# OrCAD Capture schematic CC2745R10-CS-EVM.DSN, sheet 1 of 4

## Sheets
1 1_RF: size A3; title: CC2745R10-CS-EVM
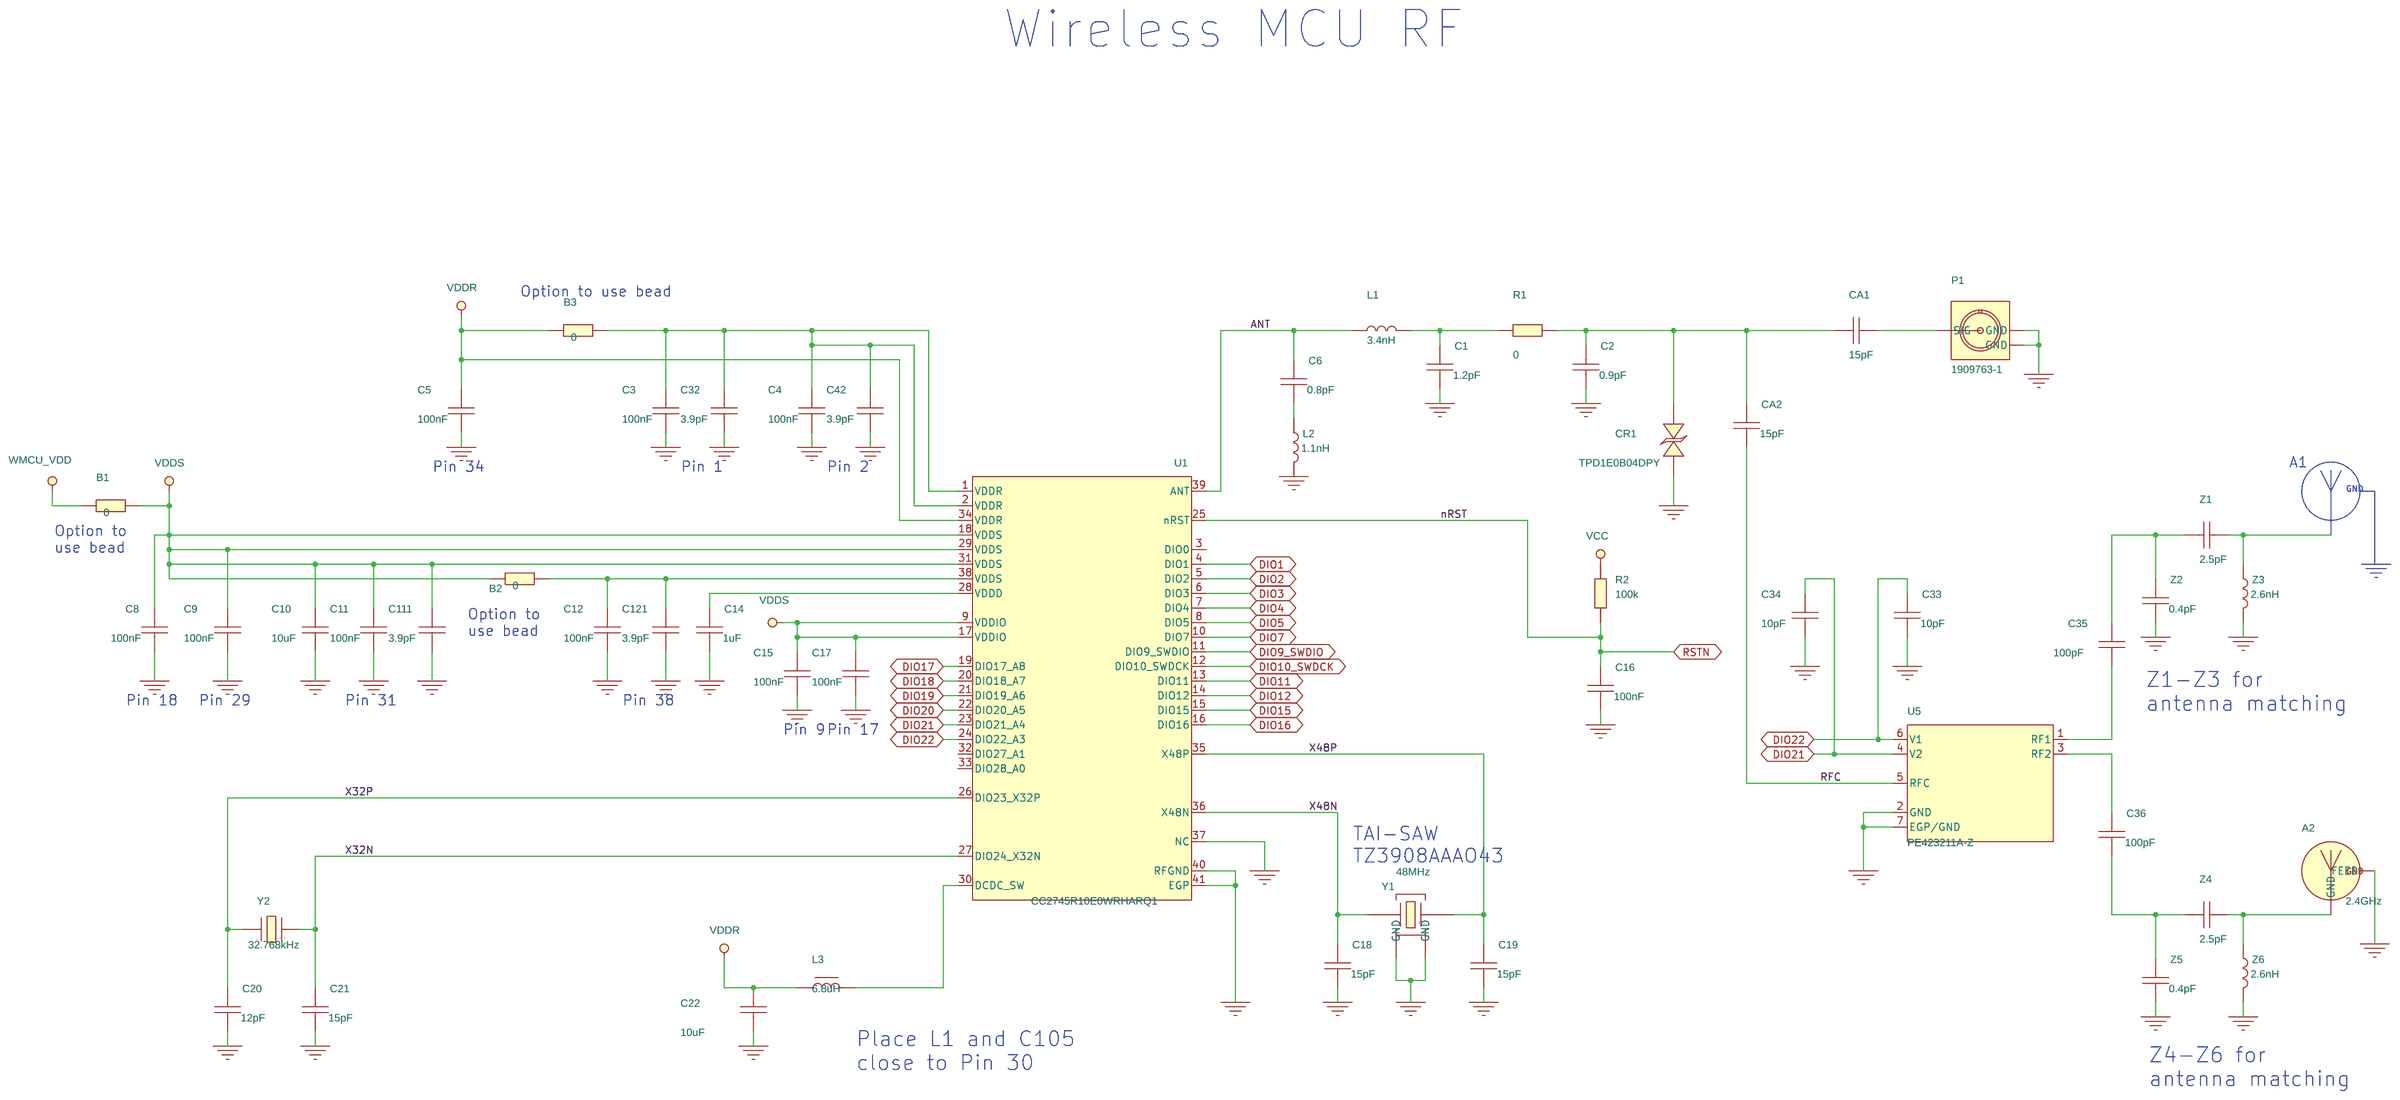
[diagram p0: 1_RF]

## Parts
A2  2.4GHz  [ANTENNA_AN043AN_B]
B1  0  [RESC0603X35B2N]
B2  0  [RESC0603X35B2N]
B3  0  [RESC0603X35B2N]
C1  1.2pF  [CAPC0603X35B2N]
C2  0.9pF  [CAPC0603X35B2N]
C3  100nF  [CAPC0603X35B2N]
C4  100nF  [CAPC0603X35B2N]
C5  100nF  [CAPC0603X35B2N]
C6  0.8pF  [CAPC0603X35B2N]
C8  100nF  [CAPC0603X35B2N]
C9  100nF  [CAPC0603X35B2N]
C10  10uF  [CAPC1608X100A2N]
C11  100nF  [CAPC0603X35B2N]
C12  100nF  [CAPC0603X35B2N]
C14  1uF  [CAPC1005X60B2N]
C15  100nF  [CAPC0603X35B2N]
C16  100nF  [CAPC0603X35B2N]
C17  100nF  [CAPC0603X35B2N]
C18  15pF  [CAPC0603X35B2N]
C19  15pF  [CAPC0603X35B2N]
C20  12pF  [CAPC0603X35B2N]
C21  15pF  [CAPC0603X35B2N]
C22  10uF  [CAPC1608X100A2N]
C32  3.9pF  [CAPC0603X35B2N]
C33  10pF  [CAPC0603X35B2N]
C34  10pF  [CAPC0603X35B2N]
C35  100pF  [CAPC0603X35B2N]
C36  100pF  [CAPC0603X35B2N]
C42  3.9pF  [CAPC0603X35B2N]
C111  3.9pF  [CAPC0603X35B2N]
C121  3.9pF  [CAPC0603X35B2N]
CA1  15pF  [CAPC0603X35B2N]
CA2  15pF  [CAPC0603X35B2N]
CR1  TPD1E0B04DPY  [SON65P100X60X45-2A2N]
L1  3.4nH  [INDC0603X33A2N]
L2  1.1nH  [INDC0603X33A2N]
L3  6.8uH  [INDC2012X150A2N]
P1  1909763-1  [TE_19097631_A2N]
R1  0  [RESC0603X35B2N]
R2  100k  [RESC0603X35B2N]
U1  CC2745R10E0WRHARQ1  [QFNFC50P600X600X100-41F2N]
U5  PE423211A-Z  [SON50P160X160X60-7C2N]
Y1  48MHz  [OSCCC205X165X50-4A2N]
Y2  32.768kHz  [XTAL_FC2012AA_A2N]
Z1  2.5pF  [CAPC0603X35B2N]
Z2  0.4pF  [CAPC0603X35B2N]
Z3  2.6nH  [INDC0603X33A2N]
Z4  2.5pF  [CAPC0603X35B2N]
Z5  0.4pF  [CAPC0603X35B2N]
Z6  2.6nH  [INDC0603X33A2N]

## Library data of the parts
A2 = ANTENNA_AN043: ANTENNA, NON COMPONENT, SMALL SIZE 2.4GHz PCB ANTENNA, NOT APPLY; ALT_SYMBOLS: ANTENNA_AN043AN_B_MIRROR,ANTENNA_AN043CN,ANTENNA_MIRROR_AN043CN; Additional Datasheet URL: N/A; CLASS: DISCRETE; Country of Origin: Missing Info; Datasheet URL: https://www.ti.com/lit/an/swra117d/swra117d.pdf; Mass: N/A; Maximum Operating Temperature: +85DEGC; Minimum Operating Temperature: -40DEGC; Mounting Type: NOT APPLY; NOTEfied URL: https://dev-webinterface.dpserver.no/item/7336948; Notes: Custom item designed upon client's request.; Packing Size: N/A; Packing Type: Missing Info; Part Number: 13-00290; Part Type: Mechanical|ANTENNA|NON COMPONENT; REACH/SVHC Compliance: Missing Info; REACH/SVHC Details: N/A; REACH/SVHC Source: N/A; REACH/SVHC Status: Missing Info; ROHS: Not Applicable; Status: Released; Texas Part Status: Under Review; Type: Mechanical; Vendor: TEXAS INSTRUMENTS; Vendor Part Number: AN043; Vendor Part Status: Active
B1-B3 R1 = RESISTOR: RESISTOR, THICK FILM, JUMPER, 0, 0R/+0.05R, 0.05W, 0.5A, -55DEGC/+155DEGC, 0201, SMD; ALT_SYMBOLS: RESC0603X35B2L,RESC0603X35B2M; Additional Datasheet URL: https://www.yageo.com/en/Home; Budgetary Price: .01936 USD; Country of Origin: Missing Info; Datasheet URL: https://www.yageo.com/upload/media/product/productsearch/datasheet/rchip/PYu-AF_51_RoHS_L_10.pdf; Lead Time: 18; Mass: N/A; Maximum Operating Temperature: +155DEGC; Maximum Temperature Coefficient: N/A; Maximum Tolerance: +0.05R; Minimum Operating Temperature: -55DEGC; Minimum Temperature Coefficient: N/A; Minimum Tolerance: 0R; Mounting Type: SMD; NOTEfied URL: https://dev-webinterface.dpserver.no/item/59954582; PCB Package: 0201; Packing Size: 50000; Packing Type: Tape & Reel; Part Number: 01-26238; Part Type: Resistor|0201|JUMPER; ROHS: Exempt; Rated Current: 0.5A; Rated Power: 0.05W; Resistor Type: THICK FILM; Status: Released; Texas Part Status: Under Review; Type: Resistor; Vendor: YAGEO; Vendor Part Number: AF0201JR-130RL; Vendor Part Status: Active
C1 = CAPACITOR: CAPACITOR, CERAMIC C0G/NP0, 1.2pF, 25V, -0.25pF/+0.25pF, -55DEGC/+125DEGC, 0201, SMD; ALT_SYMBOLS: CAPC0603X35B2L,CAPC0603X35B2M; Additional Datasheet URL: https://www.murata.com/en-us/products/productdetail?partno=GRT0335C1E1R2CA02%23; Budgetary Price: 0.005 EUR; Country of Origin: China,Japan,Philippines; Datasheet URL: https://search.murata.co.jp/Ceramy/image/img/A01X/G101/ENG/GRT0335C1E1R2CA02-01A.pdf; Dielectric Type: C0G/NP0; Lead Time: 12; Mass: 0.00033g; Maximum Operating Temperature: +125DEGC; Maximum Tolerance: +0.25pF; Minimum Operating Temperature: -55DEGC; Minimum Tolerance: -0.25pF; Mounting Type: SMD; NOTEfied URL: https://notefied-dynamic-precision.com/NOTEfiedWebInterface/part/show?partNumber=02-11179; PCB Package: 0201; Packing Size: 15000; Packing Type: Tape & Reel; Part Number: 02-11179; Part Type: Capacitor|CERAMIC|0201|STANDARD; REACH/SVHC Compliance: Compliant; REACH/SVHC Details: SVHC List Version Jun 14, 2023; REACH/SVHC Source: REACH Declaration; REACH/SVHC Status: Unaffected; ROHS: Compliant; Rated Voltage: 25V; Revision: R001; Status: Released; Texas Part Status: Under Review; Type: Capacitor; Vendor: MURATA; Vendor Part Number: GRT0335C1E1R2CA02D; Vendor Part Status: Active
C2 = CAPACITOR: CAPACITOR, CERAMIC C0G/NP0, 0.9pF, 25V, -0.05pF/+0.05pF, -55DEGC/+125DEGC, 0201, SMD; ALT_SYMBOLS: CAPC0603X35B2L,CAPC0603X35B2M; Additional Datasheet URL: N/A; Country of Origin: Missing Info; Datasheet URL: https://4donline.ihs.com/images/VipMasterIC/IC/MURE/MURE-S-A0004373697/MURE-S-A0004377215-1.pdf?hkey=52A5661711E402568146F3353EA87419; Dielectric Type: C0G/NP0; Mass: N/A; Maximum Operating Temperature: +125DEGC; Maximum Tolerance: +0.05pF; Minimum Operating Temperature: -55DEGC; Minimum Tolerance: -0.05pF; Mounting Type: SMD; NOTEfied URL: https://notefied-dynamic-precision.com/NOTEfiedWebInterface/part/show?partNumber=02-10518; PCB Package: 0201; Packing Size: 1500; Packing Type: Tape & Reel; Part Number: 02-10518; Part Type: Capacitor|CERAMIC|0201|STANDARD; REACH/SVHC Compliance: Compliant; REACH/SVHC Details: SVHC List Version Jul 08, 2021; REACH/SVHC Source: REACH Declaration; REACH/SVHC Status: Unaffected; ROHS: Compliant; Rated Voltage: 25V; Revision: R009; Status: Released; Texas Part Status: Under Review; Type: Capacitor; Vendor: MURATA; Vendor Part Number: GRT0335C1ER90WA02D; Vendor Part Status: NRND
C3-C5 C8 C9 C11 C12 C15-C17 = CAPACITOR: CAPACITOR, CERAMIC X8M, 100nF, 10V, -10%/+10%, -55DEGC/+150DEGC, 0201, SMD; ALT_SYMBOLS: CAPC0603X35B2L,CAPC0603X35B2M; Additional Datasheet URL: https://www.murata.com/en-us/products/productdetail?partno=GCM033M8ED104KE07%23; Budgetary Price: .01502 USD; Country of Origin: Missing Info; Datasheet URL: https://search.murata.co.jp/Ceramy/image/img/A01X/G101/ENG/GCM033M8ED104KE07-01A.pdf; Dielectric Type: X8M; Lead Time: 23; Mass: 0.00033g; Maximum Operating Temperature: +150DEGC; Maximum Tolerance: +10%; Minimum Operating Temperature: -55DEGC; Minimum Tolerance: -10%; Mounting Type: SMD; NOTEfied URL: https://dev-webinterface.dpserver.no/item/60514337; PCB Package: 0201; Packing Size: 15000; Packing Type: Tape & Reel; Part Number: 02-11497; Part Type: Capacitor|CERAMIC|0201|STANDARD; ROHS: Compliant; Rated Voltage: 10V; Status: Released; Texas Part Status: Under Review; Type: Capacitor; Vendor: MURATA; Vendor Part Number: GCM033M8ED104KE07D; Vendor Part Status: Active
C6 = CAPACITOR: CAPACITOR, CERAMIC C0G/NP0, 0.8pF, -0.1pF/+0.1pF, 50V, -55DEGC/+125DEGC, 0201, SMD; ALT_SYMBOLS: CAPC0603X35B2L,CAPC0603X35B2M; Additional Datasheet URL: https://pim.murata.com/en-eu/pim/details/?partNum=GCQ0335C1HR80BB01%23; Budgetary Price: .031 USD; Country of Origin: Missing Info; Datasheet URL: https://pim.murata.com/asset/pim4/ceramicCapacitorSMD/GCQ0335C1HR80BB01-01A-EN_PDF_CERAMICCAPACITORSMD?lastModifiedDatetime=20250813122647; Dielectric Type: C0G/NP0; Lead Time: 14; Mass: 0.00033g; Maximum Operating Temperature: +125DEGC; Maximum Tolerance: +0.1pF; Minimum Operating Temperature: -55DEGC; Minimum Tolerance: -0.1pF; Mounting Type: SMD; NOTEfied URL: https://webinterface.notefied-dynamic-precision.com/item/69636214; PCB Package: 0201; Packing Size: 15000; Packing Type: Tape & Reel; Part Number: 02-11784; Part Type: Capacitor|CERAMIC|0201|STANDARD; REACH/SVHC Compliance: Compliant; REACH/SVHC Details: SVHC List Version Nov 05, 2025 (251); REACH/SVHC Source: REACH Declaration; REACH/SVHC Status: Unaffected; ROHS: Compliant; Rated Voltage: 50V; Status: Released; Texas Part Status: Under Review; Type: Capacitor; Vendor: MURATA; Vendor Part Number: GCQ0335C1HR80BB01D; Vendor Part Status: Active
C10 C22 = CAPACITOR: CAPACITOR, CERAMIC X7T, 10uF, 10V, -20%/+20%, -55DEGC/+125DEGC, 0603, SMD; ALT_SYMBOLS: CAPC1608X100A2L,CAPC1608X100A2M; Additional Datasheet URL: https://www.murata.com/en-eu/products/productdetail?partno=GRT188D71A106ME13%23; Country of Origin: Missing Info; Datasheet URL: https://search.murata.co.jp/Ceramy/image/img/A01X/G101/ENG/GRT188D71A106ME13-01A.pdf; Dielectric Type: X7T; Mass: 0.0091g; Maximum Operating Temperature: +125DEGC; Maximum Tolerance: +20%; Minimum Operating Temperature: -55DEGC; Minimum Tolerance: -20%; Mounting Type: SMD; NOTEfied URL: https://notefied-dynamic-precision.com/NOTEfiedWebInterface/part/show?partNumber=02-10485; PCB Package: 0603; Packing Size: 4000; Packing Type: Tape & Reel; Part Number: 02-10485; Part Type: Capacitor|CERAMIC|0603|STANDARD; REACH/SVHC Compliance: Compliant; REACH/SVHC Details: SVHC List Version Jul 08, 2021; REACH/SVHC Source: REACH Declaration; REACH/SVHC Status: Unaffected; ROHS: Compliant; Rated Voltage: 10V; Revision: R010; Status: Released; Texas Part Status: Under Review; Type: Capacitor; Vendor: MURATA; Vendor Part Number: GRT188D71A106ME13D; Vendor Part Status: Active
C14 = CAPACITOR: CAPACITOR, CERAMIC X7R, 1uF, 6.3V, -10%/+10%, -55DEGC/+125DEGC, 0402, SMD; Additional Datasheet URL: https://www.murata.com/en-eu/products/productdetail?partno=GRT155R70J105KE01%23; Country of Origin: Missing Info; Datasheet URL: https://search.murata.co.jp/Ceramy/image/img/A01X/G101/ENG/GRT155R70J105KE01-01A.pdf; Dielectric Type: X7R; Mass: 0.0016g; Maximum Operating Temperature: +125DEGC; Maximum Tolerance: +10%; Minimum Operating Temperature: -55DEGC; Minimum Tolerance: -10%; Mounting Type: SMD; NOTEfied URL: https://notefied-dynamic-precision.com/NOTEfiedWebInterface/part/show?partNumber=02-10519; PCB Package: 0402; Packing Size: 10000; Packing Type: Tape & Reel; Part Number: 02-10519; Part Type: Capacitor|CERAMIC|0402|STANDARD; REACH/SVHC Compliance: Compliant; REACH/SVHC Details: SVHC List Version Jul 08, 2021; REACH/SVHC Source: REACH Declaration; REACH/SVHC Status: Unaffected; ROHS: Compliant; Rated Voltage: 6.3V; Revision: R010; Status: Released; Texas Part Status: Under Review; Type: Capacitor; Vendor: MURATA; Vendor Part Number: GRT155R70J105KE01D; Vendor Part Status: Active
C18 C19 CA1 = CAPACITOR: CAPACITOR, CERAMIC C0G/NP0, 15pF, 50V, -1%/+1%, -55DEGC/+125DEGC, 0201, SMD; ALT_SYMBOLS: CAPC0603X35B2L,CAPC0603X35B2M; Additional Datasheet URL: https://www.murata.com/en-eu/products/productdetail?partno=GRT0335C1H150FA02%23; Country of Origin: Missing Info; Datasheet URL: https://search.murata.co.jp/Ceramy/image/img/A01X/G101/ENG/GRT0335C1H150FA02-01A.pdf; Dielectric Type: C0G/NP0; Mass: 0.00033g; Maximum Operating Temperature: +125DEGC; Maximum Tolerance: +1%; Minimum Operating Temperature: -55DEGC; Minimum Tolerance: -1%; Mounting Type: SMD; NOTEfied URL: https://notefied-dynamic-precision.com/NOTEfiedWebInterface/part/show?partNumber=02-10511; PCB Package: 0201; Packing Size: 15000; Packing Type: Tape & Reel; Part Number: 02-10511; Part Type: Capacitor|CERAMIC|0201|PRECISION; REACH/SVHC Compliance: Compliant; REACH/SVHC Details: SVHC List Version Jul 08, 2021; REACH/SVHC Source: REACH Declaration; REACH/SVHC Status: Unaffected; ROHS: Compliant; Rated Voltage: 50V; Revision: R007; Status: Released; Texas Part Status: Under Review; Type: Capacitor; Vendor: MURATA; Vendor Part Number: GRT0335C1H150FA02D; Vendor Part Status: Active
C20 = CAPACITOR: CAPACITOR, CERAMIC C0G/NP0, 12pF, 50V, -1%/+1%, -55DEGC/+125DEGC, 0201, SMD; ALT_SYMBOLS: CAPC0603X35B2L,CAPC0603X35B2M; Additional Datasheet URL: https://www.murata.com/en-eu/products/productdetail?partno=GRT0335C1H120FA02%23; Country of Origin: Missing Info; Datasheet URL: https://search.murata.co.jp/Ceramy/image/img/A01X/G101/ENG/GRT0335C1H120FA02-01A.pdf; Dielectric Type: C0G/NP0; Mass: 0.00033g; Maximum Operating Temperature: +125DEGC; Maximum Tolerance: +1%; Minimum Operating Temperature: -55DEGC; Minimum Tolerance: -1%; Mounting Type: SMD; NOTEfied URL: https://notefied-dynamic-precision.com/NOTEfiedWebInterface/part/show?partNumber=02-10513; PCB Package: 0201; Packing Size: 15000; Packing Type: Tape & Reel; Part Number: 02-10513; Part Type: Capacitor|CERAMIC|0201|PRECISION; REACH/SVHC Compliance: Compliant; REACH/SVHC Details: SVHC List Version Jul 08, 2021; REACH/SVHC Source: REACH Declaration; REACH/SVHC Status: Unaffected; ROHS: Compliant; Rated Voltage: 50V; Revision: R010; Status: Released; Texas Part Status: Under Review; Type: Capacitor; Vendor: MURATA; Vendor Part Number: GRT0335C1H120FA02D; Vendor Part Status: Active
C21 CA2 = CAPACITOR: CAPACITOR, CERAMIC C0G/NP0, 15pF, 50V, -1%/+1%, -55DEGC/+125DEGC, 0201, SMD; ALT_SYMBOLS: CAPC0603X35B2L,CAPC0603X35B2M; Additional Datasheet URL: https://www.murata.com/en-eu/products/productdetail?partno=GRT0335C1H150FA02%23; Country of Origin: Missing Info; Datasheet URL: https://search.murata.co.jp/Ceramy/image/img/A01X/G101/ENG/GRT0335C1H150FA02-01A.pdf; Dielectric Type: C0G/NP0; Mass: 0.00033g; Maximum Operating Temperature: +125DEGC; Maximum Tolerance: +1%; Minimum Operating Temperature: -55DEGC; Minimum Tolerance: -1%; Mounting Type: SMD; NOTEfied URL: https://notefied-dynamic-precision.com/NOTEfiedWebInterface/part/show?partNumber=02-10511; PCB Package: 0201; Packing Size: 15000; Packing Type: Tape & Reel; Part Number: 02-10511; Part Type: Capacitor|CERAMIC|0201|PRECISION; REACH/SVHC Compliance: Compliant; REACH/SVHC Details: SVHC List Version Jul 08, 2021; REACH/SVHC Source: REACH Declaration; REACH/SVHC Status: Unaffected; ROHS: Compliant; Rated Voltage: 50V; Revision: R010; Status: Released; Texas Part Status: Under Review; Type: Capacitor; Vendor: MURATA; Vendor Part Number: GRT0335C1H150FA02D; Vendor Part Status: Active
C32 C42 C111 C121 = CAPACITOR: CAPACITOR, CERAMIC C0G/NP0, 3.9pF, -0.25pF/+0.25pF, 50V, -55DEGC/+125DEGC, 0201, SMD; ALT_SYMBOLS: CAPC0603X35B2L,CAPC0603X35B2M; Additional Datasheet URL: https://pim.murata.com/en-us/pim/details?partNum=GRM0335C1H3R9CA01%23; Budgetary Price: .0024 USD; Country of Origin: China, Japan, Philippines, Singapore, Thailand; Datasheet URL: https://pim.murata.com/asset/pim4/ceramicCapacitorSMD/GRM0335C1H3R9CA01-01A-EN_PDF_CERAMICCAPACITORSMD?lastModifiedDatetime=20250813140633; Dielectric Type: C0G/NP0; Lead Time: 11; Mass: 0.00033g; Maximum Operating Temperature: +125DEGC; Maximum Tolerance: +0.25pF; Minimum Operating Temperature: -55DEGC; Minimum Tolerance: -0.25pF; Mounting Type: SMD; NOTEfied URL: https://webinterface.notefied-dynamic-precision.com/item/19950881; PCB Package: 0201; Packing Size: 15000; Packing Type: Tape & Reel; Part Number: 02-09160; Part Type: Capacitor|CERAMIC|0201|STANDARD; REACH/SVHC Compliance: Compliant; REACH/SVHC Details: SVHC List Version Jan 23, 2024 (240); REACH/SVHC Source: REACH Declaration; REACH/SVHC Status: Unaffected; ROHS: Compliant; Rated Voltage: 50V; Status: Released; Texas Part Status: Under Review; Type: Capacitor; Vendor: MURATA; Vendor Part Number: GRM0335C1H3R9CA01D; Vendor Part Status: Active
C33 C34 = CAPACITOR: CAPACITOR, CERAMIC C0G/NP0, 10pF, 50V, -5%/+5%, -55DEGC/+125DEGC, 0201, SMD; ALT_SYMBOLS: CAPC0603X35B2L,CAPC0603X35B2M; Additional Datasheet URL: https://www.murata.com/en-us/products/productdetail?partno=GRT0335C1H100JA02%23; Budgetary Price: .00662 USD; Country of Origin: Missing Info; Datasheet URL: https://search.murata.co.jp/Ceramy/image/img/A01X/G101/ENG/GRT0335C1H100JA02-01A.pdf; Dielectric Type: C0G/NP0; Lead Time: 12; Mass: N/A; Maximum Operating Temperature: +125DEGC; Maximum Tolerance: +5%; Minimum Operating Temperature: -55DEGC; Minimum Tolerance: -5%; Mounting Type: SMD; NOTEfied URL: https://dev-webinterface.dpserver.no/item/62578542; PCB Package: 0201; Packing Size: 15000; Packing Type: Tape & Reel; Part Number: 02-11636; Part Type: Capacitor|CERAMIC|0201|STANDARD; REACH/SVHC Compliance: Compliant; REACH/SVHC Details: SVHC List Version Jan 21, 2025 (247); REACH/SVHC Source: REACH Declaration; REACH/SVHC Status: Unaffected; ROHS: Compliant; Rated Voltage: 50V; Status: Released; Texas Part Status: Under Review; Type: Capacitor; Vendor: MURATA; Vendor Part Number: GRT0335C1H100JA02D; Vendor Part Status: Active
C35 C36 = CAPACITOR: CAPACITOR, CERAMIC C0G/NP0, 100pF, 50V, -1%/+1%, -55DEGC/+125DEGC, 0201, SMD; ALT_SYMBOLS: CAPC0603X35B2L,CAPC0603X35B2M; Additional Datasheet URL: https://www.murata.com/en-us/products/productdetail?partno=GRT0335C1H101FA02%23; Budgetary Price: .00504 USD; Country of Origin: Missing Info; Datasheet URL: https://search.murata.co.jp/Ceramy/image/img/A01X/G101/ENG/GRT0335C1H101FA02-01A.pdf; Dielectric Type: C0G/NP0; Lead Time: 148; Mass: 0.00033g; Maximum Operating Temperature: +125DEGC; Maximum Tolerance: +1%; Minimum Operating Temperature: -55DEGC; Minimum Tolerance: -1%; Mounting Type: SMD; NOTEfied URL: https://dev-webinterface.dpserver.no/item/35968793; PCB Package: 0201; Packing Size: 15000; Packing Type: Tape & Reel; Part Number: 02-10491; Part Type: Capacitor|CERAMIC|0201|PRECISION; REACH/SVHC Compliance: Compliant; REACH/SVHC Details: SVHC List Version Jan 23, 2024 (240); REACH/SVHC Source: REACH Declaration; REACH/SVHC Status: Unaffected; ROHS: Compliant; Rated Voltage: 50V; Status: Released; Texas Part Status: Under Review; Type: Capacitor; Vendor: MURATA; Vendor Part Number: GRT0335C1H101FA02D; Vendor Part Status: Active
CR1 = DIODE_TVS_BIDIR_S: DIODE, PROTECTION, TVS, BID, 6.7V, 15W, -40DEGC/+125DEGC, X1SON2, SMD; Additional Datasheet URL: https://www.ti.com/lit/pdf/mpss034c; AutoDoc File: https://notefied-dynamic-precision.com/DB/Apps/Desktop/Item/Object.aspx?id=118028; BU Name: DYNAMIC PRECISION GDANSK; Budget Currency: USD; Budget Price: 0.08; Budgetary Price: 0.144 USD; Client Status: UNDER_REVIEW; Datasheet URL: https://www.ti.com/lit/gpn/tpd1e0b04; Datasheet URL 1: http://www.ti.com/lit/ds/symlink/tpd1e0b04.pdf; Datasheet URL 2: http://www.ti.com/lit/ml/mpss034c/mpss034c.pdf; Lead Time: 12; Mass: 0.0031g; Max Oper Temp: +125DEGC; Maximum Operating Temperature: +125DEGC; Min Oper Temp: -40DEGC; Minimum Operating Temperature: -40DEGC; Mounting Type: SMD; NOTEfied URL: https://notefied-dynamic-precision.com/NOTEfiedWebInterface/part/show?partNumber=14-06704; PCB Package: SON2; Packing Size: 10000; Packing Type: Tape & Reel; Part Number: 14-06704; Part Type: Diode|PROTECTION; REACH/SVHC Compliance: Compliant; REACH/SVHC Details: SVHC List Version Jan 12, 2017; REACH/SVHC Source: REACH Declaration; REACH/SVHC Status: Unaffected; ROHS: Compliant; Rated Power: 15W; Rated Voltage: 6.7V; Revision: R027; RoHS Status: ROHS_COMPLIANT; Rtd Power: 15W; Rtd Voltage: 6.7V; Status: Released; Texas Part Status: Under Review; Type: Diode; Vendor: TEXAS INSTRUMENTS; Vendor Part Number: TPD1E0B04DPYR; Vendor Part Status: Active; Weight: 0.0031g
L1 = INDUCTOR: INDUCTOR, RF, CHIP, 3.4nH, -0.1nH/+0.1nH, 0.45A, -55DEGC/+125DEGC, 0201, SMD; ALT_SYMBOLS: INDC0603X33A2L,INDC0603X33A2M; Additional Datasheet URL: https://www.murata.com/en-us/products/productdetail?partno=LQP03TN3N4BZ2%23; Budgetary Price: 0.02095 USD; Country of Origin: Missing Info; Datasheet URL: https://search.murata.co.jp/Ceramy/image/img/P02/JELF243C-9101.pdf; Frequency: 7GHz; Lead Time: 106; Mass: 0.0002g; Maximum Operating Temperature: +125DEGC; Maximum Tolerance: +0.1nH; Minimum Operating Temperature: -55DEGC; Minimum Tolerance: -0.1nH; Mounting Type: SMD; NOTEfied URL: https://notefied-dynamic-precision.com/NOTEfiedWebInterface/part/show?partNumber=03-08390; PCB Package: 0201; Packing Size: 15000; Packing Type: Tape & Reel; Part Number: 03-08390; Part Type: Inductor|RF|CHIP|0201; REACH/SVHC Compliance: Compliant; REACH/SVHC Details: SVHC List Version Jan 23, 2024 (240); REACH/SVHC Source: REACH Declaration; REACH/SVHC Status: Unaffected; ROHS: Compliant; Rated Current: 0.45A; Resistance: 0.25; Revision: R017; Status: Released; Texas Part Status: Under Review; Type: Inductor; Vendor: MURATA; Vendor Part Number: LQP03TN3N4BZ2D; Vendor Part Status: Active
L2 = INDUCTOR: INDUCTOR, RF, CHIP, 1.1nH, -0.1nH/+0.1nH, 0.75A, -55DEGC/+125DEGC, 0201, SMD; ALT_SYMBOLS: INDC0603X33A2L,INDC0603X33A2M; Additional Datasheet URL: https://www.murata.com/en-us/products/productdetail?partno=LQP03TN1N1BZ2%23; Budgetary Price: 0.02095 USD; Country of Origin: Missing Info; Datasheet URL: https://search.murata.co.jp/Ceramy/image/img/P02/JELF243C-9101.pdf; Frequency: 17GHz; Lead Time: 106; Mass: 0.0002g; Maximum Operating Temperature: +125DEGC; Maximum Tolerance: +0.1nH; Minimum Operating Temperature: -55DEGC; Minimum Tolerance: -0.1nH; Mounting Type: SMD; NOTEfied URL: https://notefied-dynamic-precision.com/NOTEfiedWebInterface/part/show?partNumber=03-08413; PCB Package: 0201; Packing Size: 15000; Packing Type: Tape & Reel; Part Number: 03-08413; Part Type: Inductor|RF|CHIP|0201; REACH/SVHC Compliance: Compliant; REACH/SVHC Details: SVHC List Version Jan 23, 2024 (240); REACH/SVHC Source: REACH Declaration; REACH/SVHC Status: Unaffected; ROHS: Compliant; Rated Current: 0.75A; Resistance: 0.1; Revision: R017; Status: Released; Texas Part Status: Under Review; Type: Inductor; Vendor: MURATA; Vendor Part Number: LQP03TN1N1BZ2D; Vendor Part Status: Active
L3 = IND_CORE: INDUCTOR, STANDARD, FERRITE CORE, 6.8uH, -20%/+20%, 0.11A, -55DEGC/+125DEGC, 0805, SMD; ALT_SYMBOLS: INDC2012X150A2L,INDC2012X150A2M; Additional Datasheet URL: https://product.tdk.com/en/search/inductor/inductor/smd/info?part_no=MLZ2012N6R8LTD25; Budgetary Price: 0.069 EUR; Country of Origin: Japan; Datasheet URL: https://product.tdk.com/system/files/dam/doc/product/inductor/inductor/smd/catalog/inductor_automotive_decoupling_mlz2012_en.pdf; Lead Time: 11; Mass: 0.01g; Maximum Operating Temperature: +125DEGC; Maximum Tolerance: +20%; Minimum Operating Temperature: -55DEGC; Minimum Tolerance: -20%; Mounting Type: SMD; NOTEfied URL: https://notefied-dynamic-precision.com/NOTEfiedWebInterface/part/show?partNumber=03-07971; PCB Package: 0805; Packing Size: 4000; Packing Type: Tape & Reel; Part Number: 03-07971; Part Type: Inductor|STANDARD|CHIP|0805; REACH/SVHC Compliance: Compliant; REACH/SVHC Details: SVHC List Version Jun 27, 2018 (191); REACH/SVHC Source: REACH Declaration; REACH/SVHC Status: Unaffected; ROHS: Compliant; Rated Current: 0.11A; Resistance: 0.25; Revision: R025; Status: Released; Texas Part Status: Under Review; Type: Inductor; Vendor: TDK GLOBAL; Vendor Part Number: MLZ2012N6R8LTD25; Vendor Part Status: Active
P1 = CONN_COAX_1_P_2GND: CONNECTOR, COAX, RF, MALE, STRAIGHT, 1 PIN(S), SMD; ALT_SYMBOLS: TE_19097631_A2L,TE_19097631_A2M; Additional Datasheet URL: https://www.te.com/en/product-1909763-1.html; Budgetary Price: .21237 USD; Country of Origin: China, Taiwan; Datasheet URL: https://www.te.com/commerce/DocumentDelivery/DDEController?Action=showdoc&DocId=Customer+Drawing%7F1909763%7FB3%7Fpdf%7FEnglish%7FENG_CD_1909763_B3.pdf%7F1909763-1; Lead Time: 5; Mass: 0.016g; Maximum Operating Temperature: +90DEGC; Minimum Operating Temperature: -40DEGC; Mounting Type: SMD; NOTEfied URL: https://dev-webinterface.dpserver.no/item/24854169; Number of Positions: 1; Packing Size: 5000; Packing Type: Tape & Reel; Part Number: 06-08413; Part Type: Connector|COAX|RF; ROHS: Compliant; Status: Released; Type: Connector; Vendor: TE CONNECTIVITY; Vendor Part Status: Active
R2 = RESISTOR: RESISTOR, THICK FILM, 100k, -5%/+5%, 0.05W, 50V, -55DEGC/+155DEGC, 0201, SMD; ALT_SYMBOLS: RESC0603X35B2L,RESC0603X35B2M; Additional Datasheet URL: https://www.koaspeer.com/products/resistors/general-purpose/rk73b/; Budgetary Price: 0.0106 USD; Country of Origin: Japan; Datasheet URL: https://www.koaspeer.com/pdfs/RK73B.pdf; Lead Time: 7; Mass: N/A; Maximum Operating Temperature: +155DEGC; Maximum Temperature Coefficient: +200PPM/DEGC; Maximum Tolerance: +5%; Minimum Operating Temperature: -55DEGC; Minimum Temperature Coeficient: -200PPM/DEGC; Minimum Tolerance: -5%; Mounting Type: SMD; NOTEfied URL: https://notefied-dynamic-precision.com/NOTEfiedWebInterface/part/show?partNumber=01-26031; PCB Package: 0201; Packing Size: 15000; Packing Type: Tape & Reel; Part Number: 01-26031; Part Type: Resistor|0201|STANDARD; REACH/SVHC Compliance: Compliant; REACH/SVHC Details: SVHC List Version Jan 23, 2024 (240); REACH/SVHC Source: REACH Declaration; REACH/SVHC Status: Unaffected; ROHS: Exempt; Rated Power: 0.05W; Rated Voltage: 50V; Resistor Type: THICK FILM; Revision: R001; Status: Released; Texas Part Status: Under Review; Type: Resistor; Vendor: KOA SPEER; Vendor Part Number: RK73B1HTTCM104J; Vendor Part Status: Active
U1 = IC_PROC_CC2745R1_VQFN40: IC, MICROCONTROLLER, CUSTOM, SIMPLELINK SINGLE-PROTOCOL 2.4 GHz WIRELESS MCU WITH INTEGRATED AMPLIFIER, BASELINE 6X6, VQFN40-EP, SMD; ALT_SYMBOLS: QFNFC50P600X600X100-41C2L,QFNFC50P600X600X100-41C2M,QFNFC50P600X600X100-41D2L,QFNFC50P600X600X100-41D2M,QFNFC50P600X600X100-41E2L,QFNFC50P600X600X100-41E2M; Additional Datasheet URL: https://www.ti.com/; Country of Origin: Missing Info; Datasheet URL: N/A; FPLIST: QFNFC50P600X600X100-41C2N,QFNFC50P600X600X100-41D2N,QFNFC50P600X600X100-41E2N; Mass: N/A; Maximum Operating Temperature: N/A; Minimum Operating Temperature: N/A; Mounting Type: SMD; NOTEfied URL: https://notefied-dynamic-precision.com/NOTEfiedWebInterface/part/show?partNumber=18-38063; Notes: Custom component. NOTE: exposed thermal pad is 4.7 x 4.7 mm not 4.15 mm. This change should not affect other dimensions.; PCB Package: VQFN40-EP; Packing Size: N/A; Packing Type: Missing Info; Part Number: 18-38063; Part Type: IC|MICROCONTROLLER|TEXAS INSTRUMENTS; REACH/SVHC Compliance: Missing Info; REACH/SVHC Details: N/A; REACH/SVHC Source: N/A; REACH/SVHC Status: Missing Info; ROHS: Missing Info; Revision: R006; Status: Released; Texas Part Status: Under Review; Type: IC; Vendor: TEXAS INSTRUMENTS; Vendor Part Status: Preliminary
U5 = IC_RF_PE423211_DFN6: IC, ANALOG, SPDT RF SWITCH, 2.7V TO 3.6V, DFN6-EP, SMD; ALT_SYMBOLS: SON50P160X160X60-7C2L,SON50P160X160X60-7C2M; Additional Datasheet URL: https://www.psemi.com/products/rf-switches/automotive-switches/pe423211/; Budgetary Price: .48 USD; Country of Origin: Missing Info; Datasheet URL: https://www.psemi.com/wp-content/uploads/pdf/datasheets/pe423211ds.pdf; Frequency: 300MHz TO 10.6GHz; Mass: N/A; Maximum Operating Temperature: +105DEGC; Minimum Operating Temperature: -40DEGC; Mounting Type: SMD; NOTEfied URL: https://dev-webinterface.dpserver.no/item/62518857; PCB Package: DFN6-EP; Packing Size: 3000; Packing Type: Tape & Reel; Part Number: 18-39596; Part Type: IC|ANALOG|RF|SWITCH; REACH/SVHC Compliance: Compliant; REACH/SVHC Details: SVHC List Version Jan 21, 2025 (247); REACH/SVHC Source: REACH Declaration; REACH/SVHC Status: Unaffected; ROHS: Compliant; Status: Released; Texas Part Status: Under Review; Type: IC; Vendor: PSEMI; Vendor Part Status: Active
Y1 = XTAL_4PINS_1_3: CRYSTAL, RESONATOR, 48MHz, -30PPM/+30PPM, -40DEGC/+125DEGC, SMD; ALT_SYMBOLS: OSCCC205X165X50-4A2L,OSCCC205X165X50-4A2M; Additional Datasheet URL: N/A; Capacitance: 7pF; Country of Origin: Missing Info; Datasheet URL: https://www.taisaw.com/en/product.php?pc=7; Mass: 0.0057g; Maximum Operating Temperature: +125DEGC; Maximum Stability: +30PPM; Maximum Tolerance: +5PPM; Minimum Operating Temperature: -40DEGC; Minimum Stability: -30PPM; Minimum Tolerance: -5PPM; Mounting Type: SMD; NOTEfied URL: https://notefied-dynamic-precision.com/NOTEfiedWebInterface/part/show?partNumber=12-01592; Notes: Non-standard part/non-catalogue part. Created on the basis of documentation provided by the customer (Texas Instruments).; Packing Size: 3000; Packing Type: Tape & Reel; Part Number: 12-01592; Part Type: Crystal|RESONATOR; REACH/SVHC Compliance: Missing Info; REACH/SVHC Details: N/A; REACH/SVHC Source: N/A; REACH/SVHC Status: Missing Info; ROHS: Compliant; Revision: R011; Status: Released; Texas Part Status: Under Review; Type: Crystal; Vendor: TAI-SAW; Vendor Part Number: TZ3908AAAO43; Vendor Part Status: Active
Y2 = XTAL: CRYSTAL, RESONATOR, 32.768kHz, -40DEGC/+125DEGC, 2012, SMD; ALT_SYMBOLS: XTAL_FC2012AA_A2L,XTAL_FC2012AA_A2M; Additional Datasheet URL: https://www5.epsondevice.com/en/products/crystal_unit/fc2012aa.html; Capacitance: 7pF; Country of Origin: Missing Info; Datasheet URL: https://support.epson.biz/td/api/doc_check.php?dl=app_FC2012AA&lang=en; Mass: 0.0042g; Maximum Operating Temperature: +125DEGC; Maximum Stability: N/A; Maximum Tolerance: +20PPM; Minimum Operating Temperature: -40DEGC; Minimum Stability: N/A; Minimum Tolerance: -20PPM; Mounting Type: SMD; NOTEfied URL: https://notefied-dynamic-precision.com/NOTEfiedWebInterface/part/show?partNumber=12-01782; Notes: Alias pns: X1A000181000318, FC2012AA 32.768000kHz 7 +20.0-20.0; PCB Package: 2012; Packing Size: 5000; Packing Type: Tape & Reel; Part Number: 12-01782; Part Type: Crystal|RESONATOR; REACH/SVHC Compliance: Compliant; REACH/SVHC Details: SVHC List Version Jun 14, 2023 (240); REACH/SVHC Source: REACH Declaration; REACH/SVHC Status: Unaffected; ROHS: Compliant; Revision: R001; Status: Released; Texas Part Status: Under Review; Type: Crystal; Vendor: EPSON; Vendor Part Number: FC2012AA 32.768K-70NN75KC7; Vendor Part Status: Active
Z1 Z4 = CAPACITOR: CAPACITOR, CERAMIC C0G/NP0, 2.5pF, -0.1pF/+0.1pF, 50V, -55DEGC/+125DEGC, 0201, SMD; ALT_SYMBOLS: CAPC0603X35B2L,CAPC0603X35B2M; Additional Datasheet URL: https://pim.murata.com/en-us/pim/details/?partNum=GCQ0335C1H2R5BB01%23; Budgetary Price: .02335 USD; Country of Origin: Missing Info; Datasheet URL: https://pim.murata.com/asset/pim4/ceramicCapacitorSMD/GCQ0335C1H2R5BB01-01A-EN_PDF_CERAMICCAPACITORSMD?lastModifiedDatetime=20250813122443; Dielectric Type: C0G/NP0; Lead Time: 21; Mass: N/A; Maximum Operating Temperature: +125DEGC; Maximum Tolerance: +0.1pF; Minimum Operating Temperature: -55DEGC; Minimum Tolerance: -0.1pF; Mounting Type: SMD; NOTEfied URL: https://webinterface.notefied-dynamic-precision.com/item/70813643; PCB Package: 0201; Packing Size: 15000; Packing Type: Tape & Reel; Part Number: 02-11829; Part Type: Capacitor|CERAMIC|0201|STANDARD; REACH/SVHC Compliance: Compliant; REACH/SVHC Details: SVHC List Version Feb 04, 2026 (253); REACH/SVHC Source: REACH Declaration; REACH/SVHC Status: Unaffected; ROHS: Compliant; Rated Voltage: 50V; Status: Released; Texas Part Status: Under Review; Type: Capacitor; Vendor: MURATA; Vendor Part Number: GCQ0335C1H2R5BB01D; Vendor Part Status: Active
Z2 Z5 = CAPACITOR: CAPACITOR, CERAMIC C0G/NP0, 0.4pF, 50V, -0.05pF/+0.05pF, -55DEGC/+125DEGC, 0201, SMD; ALT_SYMBOLS: CAPC0603X35B2L,CAPC0603X35B2M; Additional Datasheet URL: https://www.murata.com/en-eu/products/productdetail?partno=GCQ0335C1HR40WB01%23; Budgetary Price: 0.0139 USD; Country of Origin: Missing Info; Datasheet URL: https://search.murata.co.jp/Ceramy/image/img/A01X/G101/ENG/GCQ0335C1HR40WB01-01A.pdf; Dielectric Type: C0G/NP0; Mass: 0.00033g; Maximum Operating Temperature: +125DEGC; Maximum Tolerance: +0.05pF; Minimum Operating Temperature: -55DEGC; Minimum Tolerance: -0.05pF; Mounting Type: SMD; NOTEfied URL: https://notefied-dynamic-precision.com/NOTEfiedWebInterface/part/show?partNumber=02-11272; PCB Package: 0201; Packing Size: 15000; Packing Type: Tape & Reel; Part Number: 02-11272; Part Type: Capacitor|CERAMIC|0201|STANDARD; REACH/SVHC Compliance: Compliant; REACH/SVHC Details: SVHC List Version Jun 14, 2023 (240); REACH/SVHC Source: REACH Declaration; REACH/SVHC Status: Unaffected; ROHS: Compliant; Rated Voltage: 50V; Revision: R001; Status: Released; Texas Part Status: Under Review; Type: Capacitor; Vendor: MURATA; Vendor Part Number: GCQ0335C1HR40WB01D; Vendor Part Status: Active
Z3 Z6 = INDUCTOR: INDUCTOR, RF, NON-MAGNETIC CORE, UNSHIELDED, 2.6nH, -0.1nH/+0.1nH, 0.5A, -55DEGC/+125DEGC, 0201, SMD; ALT_SYMBOLS: INDC0603X33A2L,INDC0603X33A2M; Additional Datasheet URL: https://pim.murata.com/en-us/pim/details/?productCategoryId=inductor&partNum=LQP03TN2N6BZ2%23; Budgetary Price: .02791 USD; Country of Origin: Missing Info; Datasheet URL: https://pim.murata.com/asset/pim4/inductor/JELF243C-9101_PDF_INDUCTOR?lastModifiedDatetime=20250828163305; Frequency: 10GHz; Lead Time: 15; Mass: 0.0002g; Maximum Operating Temperature: +125DEGC; Maximum Tolerance: +0.1nH; Minimum Operating Temperature: -55DEGC; Minimum Tolerance: -0.1nH; Mounting Type: SMD; NOTEfied URL: https://webinterface.notefied-dynamic-precision.com/item/35969683; PCB Package: 0201; Packing Size: 15000; Packing Type: Tape & Reel; Part Number: 03-08398; Part Type: Inductor|RF|CHIP|0201; REACH/SVHC Compliance: Compliant; REACH/SVHC Details: SVHC List Version Feb 04, 2026 (253); REACH/SVHC Source: REACH Declaration; REACH/SVHC Status: Unaffected; ROHS: Compliant; Rated Current: 0.5A; Resistance: 0.2; Status: Released; Texas Part Status: Under Review; Type: Inductor; Vendor: MURATA; Vendor Part Number: LQP03TN2N6BZ2D; Vendor Part Status: Active

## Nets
GND: A2.2(FEED) C1.2 C2.2 C3.2 C4.2 C5.2 C8.2 C9.2 C10.2 C11.2 C12.2 C14.2 C15.2 C16.2 C17.2 C18.2 C19.2 C20.2 C21.2 C22.2 C32.2 C33.2 C34.2 C42.2 C111.2 C121.2 CR1.1 L2.2 P1.2(GND) P1.3(GND) U1.37(NC) U1.40(RFGND) U1.41(EGP) U5.2(GND) U5.7(EGP/GND) Y1.2(GND) Y1.4(GND) Z2.2 Z3.2 Z5.2 Z6.2 ; also on sheet 2 3
VDDR: B3.1 C5.1 C22.1 L3.1 U1.34(VDDR)
VDDS: B1.2 B2.1 C8.1 C9.1 C10.1 C11.1 C15.1 C17.1 C111.1 R2.2 U1.9(VDDIO) U1.17(VDDIO) U1.18(VDDS) U1.29(VDDS) U1.31(VDDS) ; also on sheet 2 3
ANT: C6.1 L1.1 U1.39(ANT)
DIO1: U1.4(DIO1) ; also on sheet 2
DIO2: U1.5(DIO2) ; also on sheet 2
DIO3: U1.6(DIO3) ; also on sheet 2
DIO4: U1.7(DIO4) ; also on sheet 2
DIO5: U1.8(DIO5) ; also on sheet 2
DIO7: U1.10(DIO7) ; also on sheet 2
DIO9_SWDIO: U1.11(DIO9_SWDIO) ; also on sheet 3
DIO10_SWDCK: U1.12(DIO10_SWDCK) ; also on sheet 3
DIO11: U1.13(DIO11) ; also on sheet 2
DIO12: U1.14(DIO12) ; also on sheet 2
DIO15: U1.15(DIO15) ; also on sheet 2
DIO16: U1.16(DIO16) ; also on sheet 2
DIO17: U1.19(DIO17_A8) ; also on sheet 2
DIO18: U1.20(DIO18_A7) ; also on sheet 2
DIO19: U1.21(DIO19_A6) ; also on sheet 2
DIO20: U1.22(DIO20_A5) ; also on sheet 2
DIO21: C34.1 U1.23(DIO21_A4) U5.4(V2)
DIO22: C33.1 U1.24(DIO22_A3) U5.6(V1)
RFC: CA2.2 U5.5(RFC)
RSTN: C16.1 R2.1 U1.25(nRST) ; also on sheet 3
WMCU_VDD: B1.1 ; also on sheet 2 3
X32N: C21.1 U1.27(DIO24_X32N) Y2.2
X32P: C20.1 U1.26(DIO23_X32P) Y2.1
X48N: C18.1 U1.36(X48N) Y1.1
X48P: C19.1 U1.35(X48P) Y1.3
N3623105: C6.2 L2.1
N3643015: B2.2 C12.1 C121.1 U1.38(VDDS)
N3643041: C14.1 U1.28(VDDD)
N3643690: B3.2 C3.1 C4.1 C32.1 C42.1 U1.1(VDDR) U1.2(VDDR)
N3644196: C1.1 L1.2 R1.2
N3644282: Z1.1 Z3.1
N3644474: C35.1 Z1.2 Z2.1
N3645221: L3.2 U1.30(DCDC_SW)
N3650163: C2.1 CA1.1 CA2.1 CR1.2 R1.1
N3905482: C36.2 Z4.2 Z5.1
N3905490: A2.1(GND) Z4.1 Z6.1
N3912800: CA1.2 P1.1(SIG)
N3922752: C35.2 U5.1(RF1)
N3990548: C36.1 U5.3(RF2)

Not connected (* = marked no-connect by the designer): U1 3(DIO0) 32(DIO27_A1) 33(DIO28_A0)

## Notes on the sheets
sheet 1
- Wireless MCU RF
- Option to use bead
- Pin 34
- Pin 1
- Pin 2
- A1
- GND
- Option to
  use bead
- Option to
  use bead
- Z1-Z3 for
  antenna matching
- Pin 18
- Pin 29
- Pin 31
- Pin 38
- Pin 9
- Pin 17
- TAI-SAW
  TZ3908AAAO43
- Place L1 and C105
  close to Pin 30
- Z4-Z6 for
  antenna matching
